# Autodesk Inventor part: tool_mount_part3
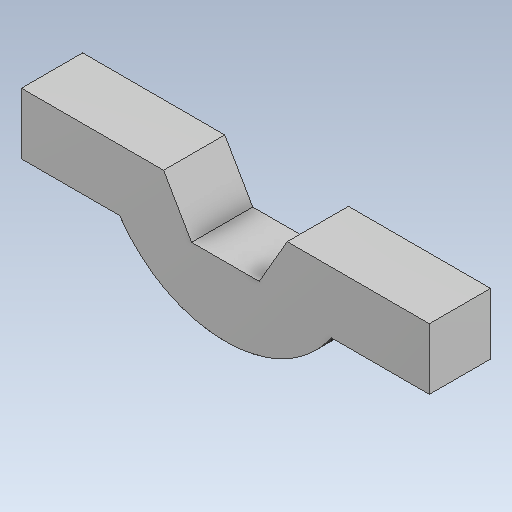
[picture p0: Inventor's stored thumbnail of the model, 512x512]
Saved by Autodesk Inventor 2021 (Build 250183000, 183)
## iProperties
Created: 2026-10
Part Number: tool_mount_part3
Material: Steel
Document SubType Name: Modeling
Designer: hp
Density: 7.85 g/cm^3
Appearance: Default
Author: hp
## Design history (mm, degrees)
feature "Body1"
body "Solid1"
